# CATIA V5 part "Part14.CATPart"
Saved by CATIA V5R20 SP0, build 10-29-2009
Part number: FV161320-7_Circlip DIN 471 - 5 x 0.6
Revision: ANY
Definition: UNKNOWN
Nomenclature: FV161320-7_Circlip DIN 471 - 5 x 0.6
Source: Unknown
Bounding box of the stored display mesh (mm): x -3.167 to 3.167, y -4.898 to 3.345, z -0.6 to 0
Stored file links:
  C:\Users\Utente\Desktop\IO LAVORO\3D X SITO CF\CUMSA\3D files FV\FV 201720\Part14.CATPart
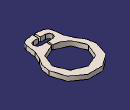
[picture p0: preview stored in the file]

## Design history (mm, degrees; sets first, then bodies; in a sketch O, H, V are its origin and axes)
Body1 "Notch" (main body)
  Solid1: solid without history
